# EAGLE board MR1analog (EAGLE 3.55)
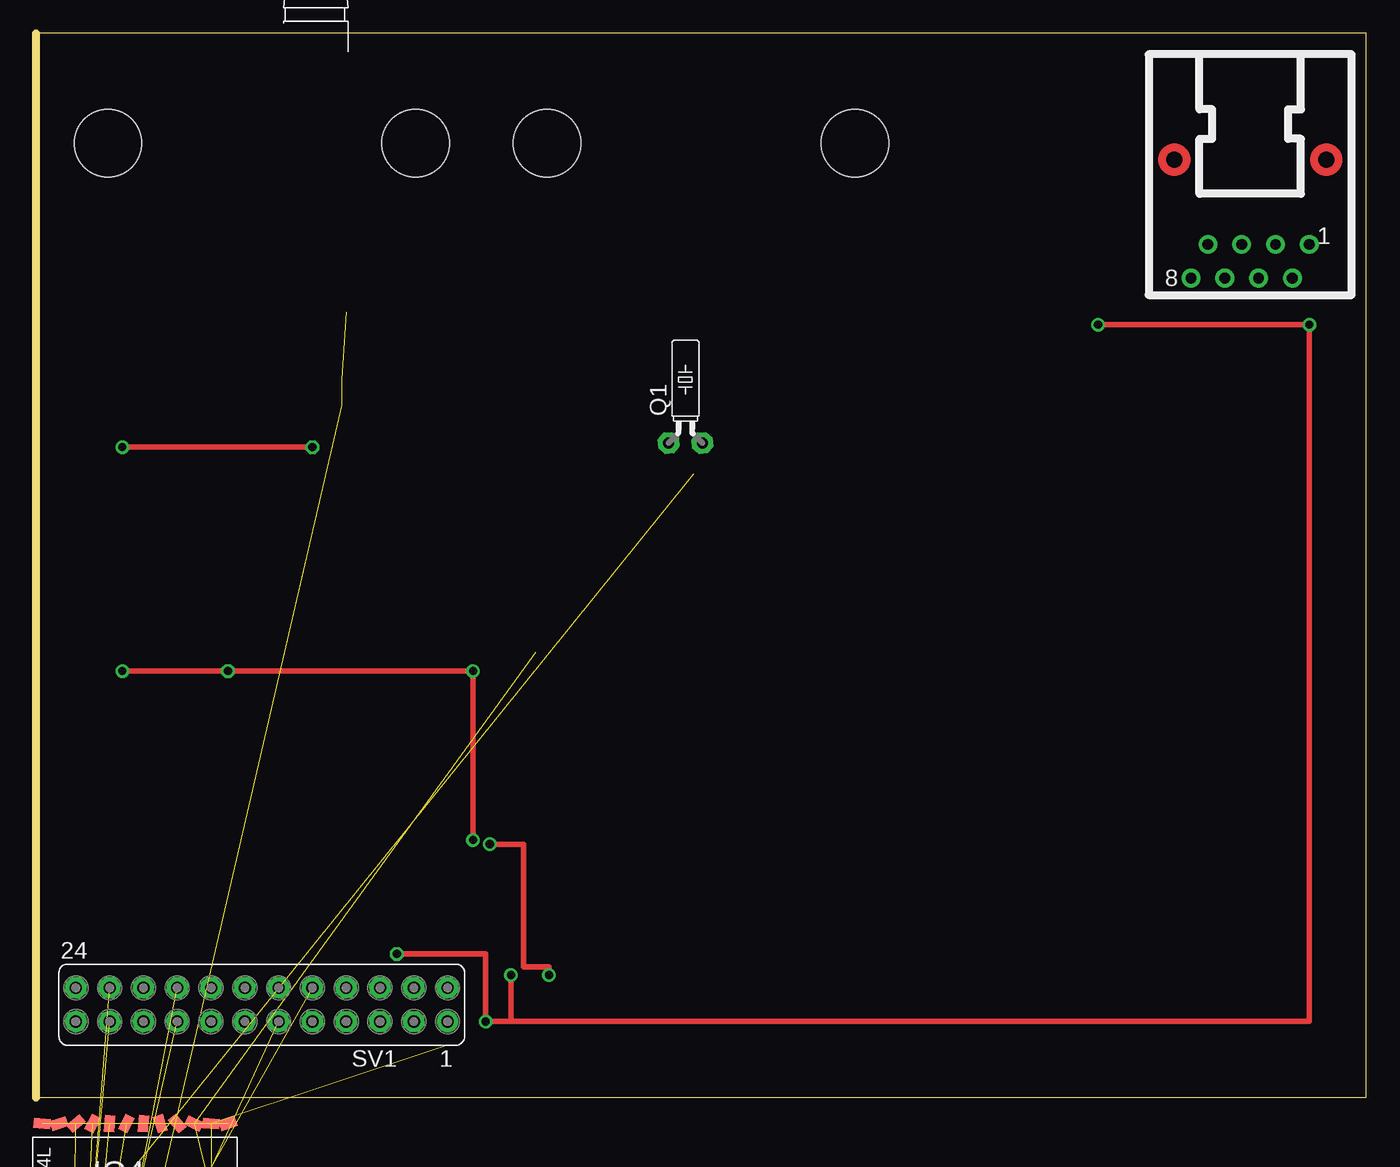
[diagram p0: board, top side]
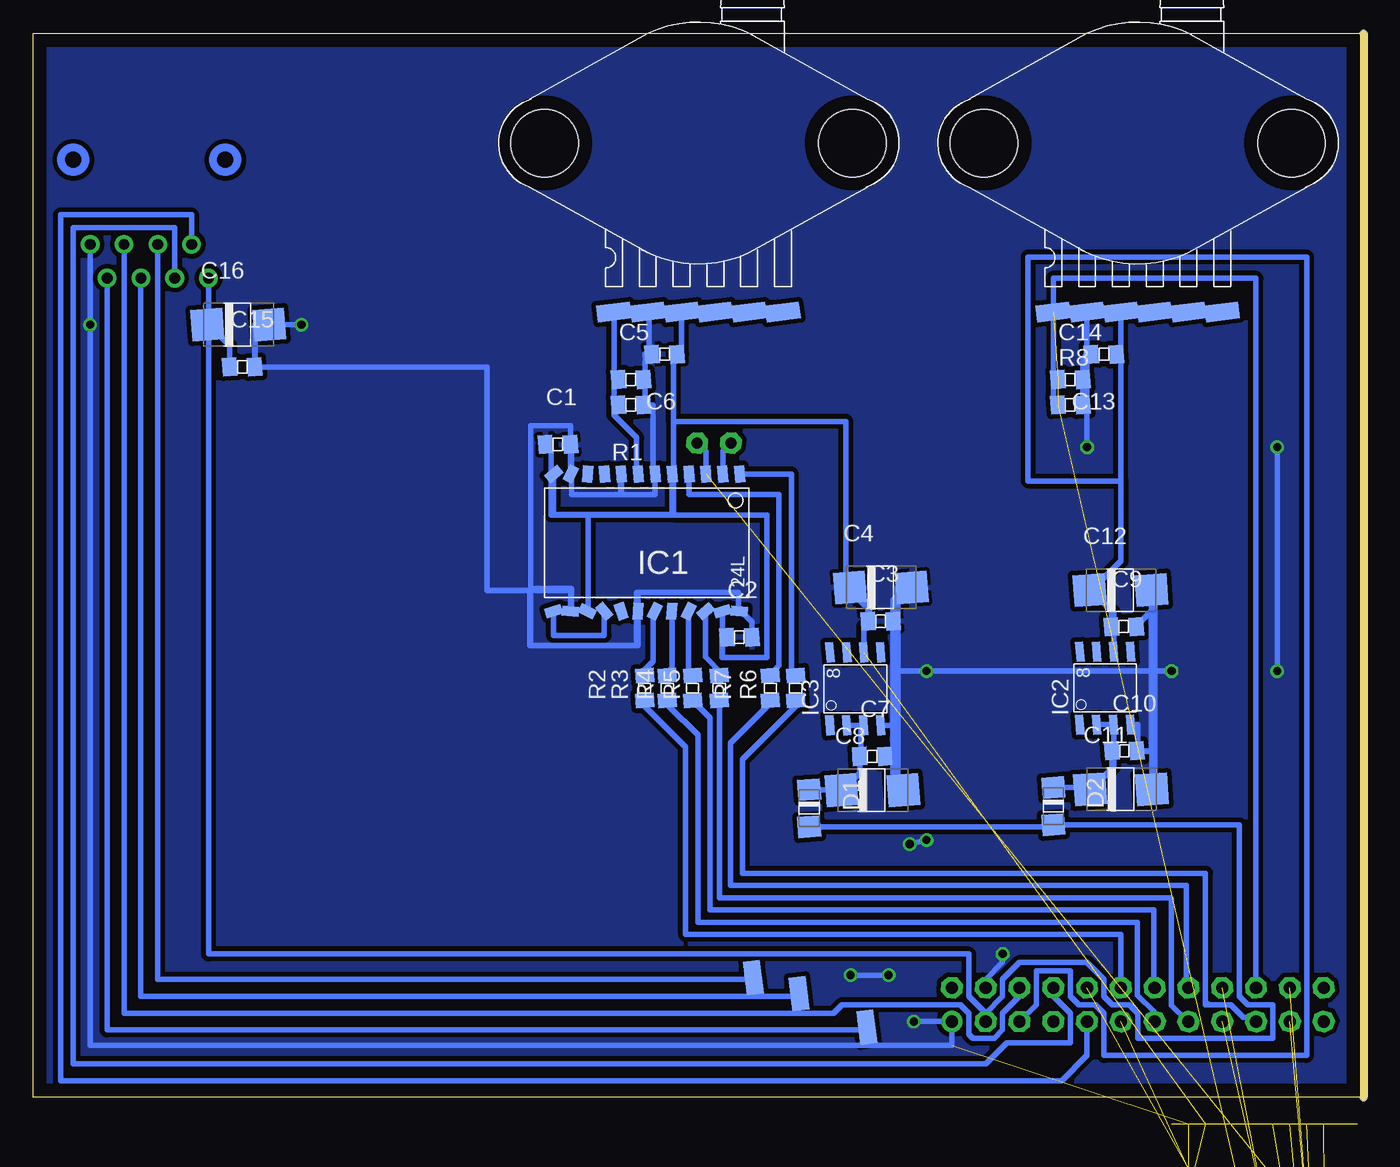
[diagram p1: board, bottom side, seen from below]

Size 100 x 80 mm. Coordinates in mm from the lower left corner, seen from the top.
Outline: 0,0 100,0 100,80 0,80 0,0
Copper layers used: Top, Bottom

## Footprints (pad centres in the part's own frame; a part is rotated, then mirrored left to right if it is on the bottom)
05 = smd 1.092 x 1.397 rotated 4.4:  0.94,0 | smd 1.092 x 1.397 rotated 4.3:  -0.94,0
32 = smd 2.388 x 2.388 rotated 4.4:  2.337,0 | smd 2.388 x 2.388 rotated 4.3:  -2.311,0
ROF_8_ = drill 0.813 pad 1.397 round:  -5.08,0;  -3.81,2.54;  -2.54,0;  -1.27,2.54;  0,0;  1.27,2.54;  2.54,0;  3.81,2.54
16 = smd 1.6 x 1.702 rotated 4.4:  1.397,0 | smd 1.6 x 1.702 rotated 4.3:  -1.397,0
IC_24 = smd 0.762 x 1.27 rotated 4.3:  -7.645,-5.283;  3.785,-5.283 | smd 0.762 x 1.27 rotated 4.4:  -6.375,-5.283;  -2.54,5.029 | smd 0.762 x 1.27 rotated 4.5:  -5.105,-5.283 | smd 0.762 x 1.27 rotated 4.6:  -3.835,-5.283 | smd 0.762 x 1.27 rotated 4.7:  -2.565,-5.283;  -1.295,-5.283 | smd 0.762 x 1.27 rotated 4.8:  -0.025,-5.283 | smd 0.762 x 1.27 rotated 4.9:  1.245,-5.283 | smd 0.762 x 1.27 rotated 5:  2.515,-5.283 | smd 0.762 x 1.27 rotated 139.3:  2.54,5.029 | smd 0.762 x 1.27 rotated 116.8:  3.81,5.029 | smd 0.762 x 1.27 rotated 94.3:  5.08,5.029 | smd 0.762 x 1.27 rotated 71.8:  6.35,5.029 | smd 0.762 x 1.27 rotated 49.3:  6.325,-5.283 | smd 0.762 x 1.27 rotated 26.8:  5.055,-5.283 | smd 0.762 x 1.27 rotated 161.8:  1.27,5.029 | smd 0.762 x 1.27 rotated 184.3:  0,5.029 | smd 0.762 x 1.27 rotated 206.8:  -1.27,5.029 | smd 0.762 x 1.27 rotated 26.9:  -3.81,5.029 | smd 0.762 x 1.27 rotated 49.4:  -5.08,5.029 | smd 0.762 x 1.27 rotated 71.9:  -6.35,5.029 | smd 0.762 x 1.27 rotated 94.4:  -7.62,5.029
8 = smd 0.61 x 1.524 rotated 4.3:  -2.54,-2.743 | smd 0.61 x 1.524 rotated 4.9:  -2.54,2.743 | smd 0.61 x 1.524 rotated 4.4:  -1.27,-2.743 | smd 0.61 x 1.524 rotated 4.5:  0,-2.743 | smd 0.61 x 1.524 rotated 4.8:  -1.27,2.743 | smd 0.61 x 1.524 rotated 4.7:  0,2.743;  1.27,2.743 | smd 0.61 x 1.524 rotated 4.6:  1.27,-2.743
D127X2 = smd 2.54 x 1.27 rotated 97:  0,0
7B-04 = smd 1.27 x 2.54 rotated 97:  -6.35,-12.7;  -3.81,-12.7;  -1.27,-12.7;  1.27,-12.7;  3.81,-12.7;  6.35,-12.7 | hole 5.08: 11.557,0; -11.557,0
7C-05 = smd 1.27 x 2.54 rotated 97:  -7.62,-11.43;  -5.08,-11.43;  -2.54,-11.43;  0,-11.43;  2.54,-11.43;  5.08,-11.43 | hole 5.08: 10.287,1.27; -12.827,1.27
26H = drill 0.813 pad 1.6 octagon:  -1.27,0;  1.27,0
12-2 = drill 0.914 pad 1.6 round:  -13.97,1.27 | drill 0.914 pad 1.6 octagon:  -13.97,-1.27;  -11.43,1.27;  -11.43,-1.27;  -8.89,1.27;  -8.89,-1.27;  -6.35,1.27;  -6.35,-1.27;  -3.81,1.27;  -3.81,-1.27;  -1.27,1.27;  -1.27,-1.27;  1.27,1.27;  1.27,-1.27;  3.81,1.27;  3.81,-1.27;  6.35,1.27;  6.35,-1.27;  8.89,1.27;  8.89,-1.27;  11.43,1.27;  11.43,-1.27;  13.97,1.27;  13.97,-1.27

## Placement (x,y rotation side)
C1  100n  [05]  60.56,49.1 0 bottom
C2  100n  [05]  46.93,34.6 0 bottom
C3  100n  [05]  36.31,35.8 0 bottom
C4  100u  [32]  36.31,38.34 0 bottom
C5  10p  [05]  55.08,53.97 0 bottom
C6  100n  [05]  52.54,55.88 180 bottom
C7  100n  [05]  36.94,25.64 0 bottom
C8  100u  [32]  36.94,23.1 0 bottom
C9  100n  [05]  18.03,35.4 0 bottom
C10  100n  [05]  17.99,26.06 0 bottom
C11  100u  [32]  18.25,23.17 0 bottom
C12  100u  [32]  18.29,38.14 0 bottom
C13  100n  [05]  19.52,55.88 180 bottom
C14  10p  [05]  22.06,53.97 0 bottom
C15  100n  [05]  84.29,54.92 0 bottom
C16  100u  [32]  84.61,58.1 0 bottom
C17  100n  [05]  not placed on the board
C18  100n  [05]  not placed on the board
CON1  8_8POLWEST  [ROF_8_]  90.64,64.13 180 top
D1  DIODE_3216  [16]  41.68,21.74 270 bottom
D2  DIODE_3216  [16]  23.33,21.9 270 bottom
IC1  AD7711AAR  [IC_24]  54.55,41.59 180 bottom
IC2  REF195GS  [8]  18.8,30.77 0 bottom
IC3  REF195GS  [8]  37.58,30.72 0 bottom
IC4  AD7711AAR  [IC_24]  8.09,-6.99 0 top
PAD1  switcher_R  [D127X2]  45.87,9.01 0 bottom
PAD2  switcher_L  [D127X2]  42.45,7.81 0 bottom
PAD3  lautspeaker  [D127X2]  37.35,5.28 180 bottom
PS1  MPX4100AP  [7B-04]  50,71.75 0 bottom
PS2  MPX5010DP  [7C-05]  15.71,70.48 0 bottom
Q1  10MHz  [26H]  48.83,49.21 0 top
R1  1M  [05]  55.08,52.07 180 bottom
R2  390  [05]  54.05,30.78 90 bottom
R3  390  [05]  52.35,30.78 90 bottom
R4  390  [05]  50.44,30.78 90 bottom
R5  390  [05]  48.44,30.78 90 bottom
R6  390  [05]  42.69,30.78 90 bottom
R7  390  [05]  44.59,30.78 90 bottom
R8  10M  [05]  22.06,52.07 0 bottom
R9  390  [05]  not placed on the board
R10  390  [05]  not placed on the board
R11  390  [05]  not placed on the board
R12  390  [05]  not placed on the board
R13  390  [05]  not placed on the board
R14  390  [05]  not placed on the board
SV1  FE12-2  [12-2]  16.98,6.98 180 top

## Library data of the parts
C1-C18 D1 D2 PAD1-PAD3 R1-R14 = SMD
CON1 = WESTERN
IC1-IC4 = Analog
PS1 PS2 = MOTOROLA
Q1 = QUARTZ
SV1 = CON-LSTA

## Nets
+5V: C1. C2. C3. C4. C6. C17. C18. IC1. IC3. IC4. PS1.
+5V/1: C9. C12. C13. IC2. PS2. SV1.
+UB: C15. C16. CON1. D1. D2. SV1.
AGND: C1. C2. C3. C4. C5. C6. C7. C8. C9. C10. C11. C12. C13. C14. C15. C16. C17. C18. CON1. IC1. IC2. IC3. IC4. PS1. PS2. R1. R8. SV1.
N$1: IC1. Q1.
N$2: IC1. IC4. Q1.
N$3: IC1. R2.
N$4: C14. IC4. PS2. R8.
N$5: IC1. R3.
N$6: IC1. R4.
N$7: IC1. R5.
N$8: C7. C8. D1. IC3.
N$9: IC1. R6.
N$10: IC1. R7.
N$11: IC1.
N$12: C10. C11. D2. IC2.
N$13: R5. SV1.
N$14: SV1.
N$15: CON1. PAD3.
N$16: C5. IC1. PS1. R1.
N$17: R3. SV1.
N$18: R2. SV1.
N$19: R14. SV1.
N$20: R4. SV1.
N$21: R13. SV1.
N$22: R6. SV1.
N$23: R7. SV1.
N$24: CON1. PAD1.
N$25: CON1. PAD2.
N$26: CON1. SV1.
N$27: CON1. SV1.
N$28: CON1. SV1.
N$29: IC4. R9.
N$30: IC4. R10.
N$31: IC4. R11.
N$32: IC4. R12.
N$33: IC4. R13.
N$34: IC4. R14.
N$35: IC4.
N$36: R12. SV1.
N$37: R11. SV1.
N$38: R10. SV1.
N$39: R9. SV1.

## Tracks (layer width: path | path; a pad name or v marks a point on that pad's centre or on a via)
+5V  (6 unrouted)
  Bottom 0.406: 51.27,55.88 51.27,59.05 | 51.27,55.88 C6. | 61.07,47.15 61.07,49.01 61.58,49.01 61.58,48.99 | 60.89,43.84 52,43.84 52,46.87 51.98,46.87 51.89,46.87 51.89,50.83 | 60.89,43.84 60.89,46.66 61.07,46.66 61.07,46.85 | 48.2,34.6 48.2,36.56 | 37.16,35.83 37.16,35.8 C3. 37.24,36.74 38.85,38.34 C4. 38.62,38.28 38.92,38.28 38.92,50.83 51.89,50.83 | 37.57,33.47 37.57,35.42 37.16,35.83 | 37.16,35.83 37.16,36.75 38.69,38.28 | 51.89,50.83 51.89,55.72 51.28,55.72 51.28,55.88 51.27,55.88 | 51.27,55.88 51.89,55.88 51.89,50.83 | 48.2,34.6 48.2,33.07 44.85,33.07 | 48.22,34.6 48.22,33.07 44.85,33.07 | 48.22,34.6 48.2,34.6 | C2. 48.22,34.6 | 61.58,48.99 61.58,48.81 61.07,48.81 61.07,47.15 | 61.07,48.99 61.58,48.99 | 51.89,50.83 51.89,56.03 51.28,56.03 | 51.89,43.79 61.07,43.79 61.07,46.85 | 51.89,50.83 51.89,55.42 51.28,56.03 | 51.28,56.03 51.28,59.4 | 58.35,36.56 58.32,36.56 58.32,43.84 60.89,43.84 | 44.85,33.07 44.85,43.79 51.89,43.79 | 51.89,50.83 51.89,43.79 | 61.07,47.15 61.07,48.99 | 61.07,48.99 61.5,48.99 | 61.07,46.85 61.07,47.15 | 60.87,46.87 60.87,47.15 61.07,47.15 | 61.58,48.99 61.5,48.99 | 61.5,48.99 C1. | 61.58,48.99 61.68,48.99
+5V/1
  Bottom 0.406: 18.25,55.88 18.25,59.05 | 18.25,55.88 C13. | C12. 20.52,38.14 20.47,38.1 | 18.8,33.51 18.8,36.42 20.47,38.1 | C9. 18.97,36.59 20.47,38.1 | 18.25,46.35 18.25,55.88 | 25.87,5.71 24.6,6.98 24.6,9.52 22.06,9.52 22.06,7.62 21.42,6.98 20.15,6.98 19.52,6.34 19.52,3.17 4.28,3.17 4.28,63.18 25.23,63.18 25.23,46.35 18.25,46.35 | 18.25,46.35 18.25,40.32 20.47,38.1
+UB
  Bottom 0.406: 86.83,58.1 CON1. | 86.83,58.1 C16. | C15. 85.23,56.5 86.83,58.1 | 86.83,58.1 86.83,10.79 29.68,10.79 29.68,7.62 28.41,6.34 | 23.33,20.34 23.33,20.5 9.36,20.5 9.36,7.62 8.73,6.98 6.82,6.98 6.82,4.44 16.98,4.44 16.98,6.34 17.61,6.98 18.88,6.98 19.52,7.62 19.52,8.89 20.79,10.16 25.87,10.16 27.14,8.89 27.14,7.62 28.41,6.34 | 23.33,20.34 41.68,20.34 | 23.33,20.34 23.33,20.31 | 28.41,6.34 28.41,5.71
AGND  (via drill 0.61 pad 1.02)  (8 unrouted)
  Top 0.406: v95.72,58.1 v79.84,58.1 v95.72,58.1 | v95.72,58.1 95.72,5.71 v33.81,5.71 | v27.14,10.79 33.81,10.79 v33.81,5.71 | v6.5,48.89 v20.79,48.89 | v6.5,32.06 v14.44,32.06 v32.85,32.06 v32.85,19.36 | v34.12,19.04 36.66,19.04 36.66,9.84 38.57,9.84 v38.57,9.2 | v35.71,9.2 35.71,5.71 v33.81,5.71
  Bottom 0.406: 20.79,55.88 21.12,55.55 21.12,53.97 21.12,52.4 20.79,52.07 | 20.79,55.88 20.79,59.05 | 20.79,55.88 20.46,55.88 | 20.79,52.07 20.79,55.88 | 34.4,23.1 34.53,22.97 35.02,22.97 | 35.02,22.97 35.33,22.97 35.33,25.64 36,25.64 35.02,25.64 35.02,22.97 | 33.97,38.34 34.4,38.34 35.04,37.71 | 35.37,35.8 35.37,37.38 35.04,37.71 | 34.4,23.1 34.6,23.1 | 35.37,35.8 35.37,24.07 34.4,23.1 | 35.04,37.71 35.04,27.98 | 35.04,37.71 33.77,37.71 33.77,38.34 | 35.04,27.98 36.31,27.98 | 35.04,38.34 35.04,27.98 | 35.37,35.8 35.04,35.8 35.04,38.34 | 35.04,38.34 33.77,38.34 | 54.55,36.56 54.55,33.99 | 59.54,46.85 59.6,46.85 59.6,46.87 | 59.54,46.85 59.54,45.32 55.79,45.32 55.79,46.87 55.79,46.85 55.87,46.85 55.87,45.32 53.25,45.32 53.25,46.87 53.42,46.87 | 54.03,53.89 54.03,52.07 R1. 53.42,52.07 53.42,46.87 | 53.42,46.87 53.42,46.85 | 54.03,53.89 54.03,53.97 54.14,53.97 | 54.03,53.89 54.03,55.88 53.48,55.88 53.73,55.88 53.73,59.05 53.81,59.05 | 59.54,46.85 59.54,46.87 59.6,46.87 | 59.54,46.85 59.54,49.1 59.62,49.1 59.62,50.52 62.6,50.52 | 59.6,46.87 59.6,50.52 62.6,50.52 | 62.6,38.28 62.6,50.52 | 62.6,38.28 59.54,38.28 59.54,36.44 | 59.54,36.44 59.62,36.44 59.62,36.56 59.62,38.28 62.6,38.28 | 45.99,35.74 45.99,34.6 45.99,35.74 | 45.99,35.74 46.8,36.56 IC1. 46.92,36.44 46.99,36.44 46.99,36.75 | 62.6,38.28 62.6,33.99 54.64,33.99 | 54.55,36.56 54.55,36.44 54.64,36.44 54.64,33.99 | 54.55,36.56 54.55,37.97 46.99,37.97 | 33.77,38.34 35.02,38.34 35.02,22.97 | 35.02,22.97 34.41,22.97 | 46.99,36.75 45.99,35.74 | 46.99,37.97 46.99,36.75 | 46.99,37.97 54.64,37.97 54.64,33.99 | 54.64,33.99 55.56,33.99 55.56,33.97 57.94,33.97 | 30.95,5.71 30.95,5.53 31.08,5.53
  Bottom 0.406: 30.95,5.71 30.95,3.94 95.72,3.94 v95.72,58.1 95.72,64.13 | 59.54,36.44 59.54,38.1 65.88,38.1 | 83.34,54.92 83.35,54.92 83.35,58.1 82.27,58.1 v79.84,58.1 83.34,58.1 83.34,54.92 | 65.88,38.1 62.7,38.1 62.7,33.97 57.94,33.97 | 65.88,38.1 65.88,54.92 83.34,54.92 | v33.81,5.71 30.95,5.71 | 16.98,26.06 16.98,26.03 | 16.98,26.06 17.05,26.06 15.71,26.06 15.71,23.17 15.91,23.17 15.91,37.98 16.03,38.1 | 16.98,27.93 16.98,28.03 17.53,28.03 17.53,27.93 | 16.98,26.06 16.98,27.93 | 17.09,35.4 17.09,35.45 15.95,36.59 15.95,38.14 15.95,26.03 16.98,26.03 | 16.98,26.03 16.98,27.93 | 17.53,27.93 17.61,27.93 | 16.98,27.93 17.53,27.93 | 16.03,38.1 16.03,37.78 | 16.03,38.1 16.03,39.05 15.71,39.05 15.71,32.06 | 20.79,52.07 21.12,52.07 | v20.79,48.89 20.79,52.07 | 34.4,23.1 34.4,23.17 35.08,23.17 35.08,32.06 v32.85,32.06 v14.44,32.06 15.71,32.06 | v33.81,5.71 30.95,5.71 | 15.71,32.06 15.71,22.86 | v33.81,5.71 30.95,5.71 | 28.41,8.25 28.41,8.89 27.14,10.16 v27.14,10.79 | v33.81,5.71 30.95,5.71 | 54.54,34.13 54.54,34.19 54.76,33.97 57.94,33.97 | v6.5,32.06 v6.5,48.89 | v34.12,19.04 v32.85,19.36 | v35.71,9.2 v38.57,9.2
  pour Bottom (isolate 0.356): -0.17,80.64 100.48,80.64 100.48,-0.64 -0.17,-0.32
N$1
  Bottom 0.406: 48.17,46.87 48.17,48.6 47.56,49.21
N$2  (1 unrouted)
  Bottom 0.406: 49.44,46.87 49.44,48.55 Q1.
N$3
  Bottom 0.406: 54.05,31.72 54.05,32.14 53.42,32.77 53.42,36.44 53.3,36.56 53.27,36.56
N$4  (3 unrouted)
N$5
  Bottom 0.406: 52.35,31.72 52.37,31.72 52.5,31.85 52,32.35 52,36.56
N$6
  Bottom 0.406: 50.44,31.54 50.36,31.54 | 50.44,31.72 50.44,31.54 | 50.73,36.56 50.73,31.54 50.44,31.54
N$7
  Bottom 0.406: 48.44,31.72 48.35,31.72 48.22,31.85 49.46,33.1 49.46,36.56
N$8
  Bottom 0.406: 37.57,27.98 37.57,28.18 37.78,27.98 | 37.78,27.98 38.85,27.98 | 39.31,23.14 39.31,23.1 C8. 39.25,23.03 | 39.31,23.14 D1. | 39.31,23.14 39.31,23.28 | 39.25,23.03 39.31,22.97 | 39.25,23.03 37.88,24.4 C7. 37.78,25.75 37.78,27.98
N$9
  Bottom 0.406: 46.9,46.87 43.01,46.87 43.01,32.16 42.69,31.83 42.69,31.72
N$10
  Bottom 0.406: 50.71,46.87 50.71,45.32 43.93,45.32 43.93,32.46 44.59,31.8 44.59,31.72
N$11
  Bottom 0.406: 60.89,36.56 60.89,34.74 57.09,34.74 57.09,36.56 57.09,36.51
N$12
  Bottom 0.406: 18.88,28.03 18.8,28.03 18.8,24.85 18.88,24.76 | 18.88,28.03 20.07,28.03 | 18.88,28.03 18.88,27.93 | 20.47,23.17 18.93,24.72 C10. 18.88,26.03 18.88,24.76 | C11. 20.47,23.17 | 20.47,23.17 18.88,24.76 | D2. 20.34,23.3 18.88,24.76
N$13
  Bottom 0.406: R5. 48.44,15.02 14.55,15.02 14.45,14.92 14.44,14.92 14.44,6.95 13.2,5.71 13.17,5.71
N$14
  Bottom 0.406: 23.33,53.97 23.33,52.07 23.33,61.59 8.09,61.59 8.09,8.25
N$15
  Bottom 0.406: 94.45,61.59 94.45,5.08 37.35,5.08 PAD3.
N$16
  Bottom 0.406: 56.35,52.07 56.35,59.05 | 56.35,52.07 56.02,52.07 | C5. 56.35,53.97 56.35,52.07 | 56.35,51.31 56.35,52.07 | 54.64,49.6 56.35,51.31 | 56.35,52.07 56.35,51.31 | 56.17,51.13 56.35,51.31 | 56.17,51.13 | 54.64,49.6 56.17,51.13 | 54.52,46.87 54.62,46.87 54.64,46.85 54.64,49.6
N$17
  Bottom 0.406: R3. 52.2,29.68 52.2,29.4 50.05,27.26 50.05,13.18 17,13.18 17,7.69 15.77,6.47 15.77,6.41 15.71,6.34 15.71,5.71
N$18
  Bottom 0.406: R2. 54.05,29.4 54.03,29.4 50.97,26.34 50.97,12.26 18.25,12.26 18.25,8.25
N$19  (1 unrouted)
N$20
  Bottom 0.406: R4. 49.13,28.53 49.13,14.1 15.77,14.1 15.77,8.25 15.71,8.25
N$21  (1 unrouted)
N$22
  Bottom 0.406: R6. 42.69,29.42 46.69,25.42 46.69,16.85 11.89,16.85 11.89,7.06 11.66,7.06 11.58,6.98 | 11.58,6.98 10,6.98 9.04,6.03 8.41,6.03 8.09,5.71 8.09,5.8 | 11.58,6.98 11.9,6.98
N$23
  Bottom 0.406: R7. 44.59,29.66 47.6,26.65 47.6,15.93 13.33,15.93 13.33,8.25 13.17,8.25
N$24
  Bottom 0.406: PAD1. 45.87,8.89 90.64,8.89 90.64,64.13
N$25
  Bottom 0.406: 42.45,7.62 42.38,7.62 | PAD2. 42.45,7.62 | 91.91,61.59 91.91,7.62 42.45,7.62
N$26
  Bottom 0.406: 93.18,64.13 93.18,6.34 39.84,6.34 39.2,6.98 30.31,6.98 29.68,6.34 29.68,4.76 29.36,4.44 27.77,4.44 27.14,5.08 27.14,6.34 25.87,7.62 25.87,8.25
N$27
  Bottom 0.406: 89.37,61.59 89.37,65.4 96.99,65.4 96.99,2.54 28.41,2.54 26.82,4.12 22.06,4.12 22.06,6.34 23.33,7.62 23.33,8.25
N$28
  Bottom 0.406: 88.1,64.13 88.1,66.35 97.94,66.35 97.94,1.27 22.7,1.27 20.79,3.17 20.79,5.71
N$29  (1 unrouted)
N$30  (1 unrouted)
N$31  (1 unrouted)
N$32  (1 unrouted)
N$33  (1 unrouted)
N$34  (1 unrouted)
N$35  (1 unrouted)
N$36  (1 unrouted)
N$37  (1 unrouted)
N$38  (1 unrouted)
N$39  (1 unrouted)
